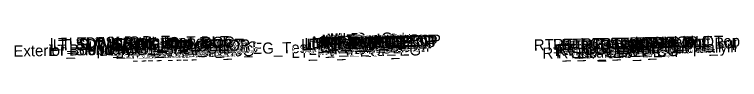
# Model space of a CAD drawing. Extents: x 118 to 4243, y 0 to 9511.
# Drawn here: x 1130.7 to 1260.3, y 1500.7 to 1505.9 of the extents above; entities that cross this region are included whole.
import ezdxf

# ---------------------------------------------------------------- set-up
doc = ezdxf.new("R2010")
doc.units = 0
doc.layers.add('Scratch_Level_0', color=7, linetype='Continuous')

msp = doc.modelspace()

# ---------------------------------------------------------------- texts
at = {"layer": 'Scratch_Level_0'}
for s, p in [('LT_SDWK_Out_Top', (1137.01, 1502.91)), ('LT_SDWK_Out_Bot', (1137.04, 1502.58)), ('LT_Sub_Trench_Out_DLT', (1137.57, 1502.67)), ('LT_CSLP_Pnt', (1140.44, 1502.99)), ('LT_SDWK_In_Top', (1143.63, 1502.85)), ('LT_CG_Top_Face', (1147.53, 1502.75)), ('LT_CG_Top_BOC', (1148.05, 1502.77)), ('LT_PV2_IEEOP', (1181.97, 1502.76)), ('LT_PV1_IEEOP', (1182.54, 1502.9)), ('LT_PV2_PGL1', (1182.9, 1502.78)), ('LT_PV2_PGL', (1183.23, 1502.79)), ('LT_PV1_PGL', (1183.8, 1503.05)), ('MI_Face In', (1183.92, 1503.22)), ('RT_PV2_OEEOP', (1185.28, 1502.99)), ('RT_PV3_OEEOP', (1185.28, 1502.66)), ('MI_Top In', (1185.63, 1503.49)), ('RT_PV1_OEEOP', (1185.85, 1503.13)), ('RT_PV2_IEEOP', (1185.93, 1503)), ('MI_Face Out', (1186.28, 1503.43)), ('MI_Top Out', (1186.49, 1503.7)), ('RT_PV1_IEEOP', (1186.49, 1503.14)), ('RT_PV2_PGL1', (1186.86, 1503.02)), ('RT_PV3_PGL1', (1186.86, 1502.69)), ('MI_Crown', (1187.09, 1503.76)), ('RT_PV2_PGL', (1187.19, 1503.03)), ('MI_Bot Out', (1187.28, 1503.28)), ('RT_PV1_PGL', (1187.75, 1503.29)), ('RT_Sub_Trench_Out_DLT', (1223.56, 1502.67)), ('RT_CG_Top_Face', (1226.99, 1502.74)), ('RT_CG_Top_BOC', (1228.51, 1502.76)), ('RT_SDWK_In_Top', (1232.08, 1502.85)), ('RT_SDWK_Out_Top', (1235.46, 1502.91)), ('RT_SDWK_Out_Bot', (1235.49, 1502.58)), ('RT_Shld_O', (1241.81, 1503.03)), ('CSLP_Pnt', (1242.64, 1503.05)), ('Exterior Boundary', (1130.51, 1501.57)), ('LT_Slope_Fill', (1136.89, 1501.7)), ('LT_SDWK_In_Bot', (1143.66, 1502.51)), ('LT_CG1_Shelf_Out', (1145.82, 1501.71)), ('LT_PV_Sub_Tie_Out', (1147.23, 1501.79)), ('LT_CG_Bot_BOC', (1148.09, 1501.75)), ('LT_CG_Top_Gut', (1148.51, 1502.26)), ('LT_Sub_OEOT_CG', (1149.64, 1501.2)), ('LT_PV_OEEOP_EG', (1149.82, 1501.84)), ('LT_PV2_OEEOP', (1151.58, 1502.16)), ('LT_PV3_OEEOP', (1151.58, 1501.82)), ('LT_PV1_OEEOP', (1152.15, 1502.29)), ('LT_CG_Bot_IE', (1152.19, 1501.84)), ('LT_PV2_OEOT', (1152.45, 1502.17)), ('LT_PV3_OEOT', (1152.45, 1501.84)), ('LT_PV1_OEOT', (1153.01, 1502.44)), ('LT_PV_EG_TestPt', (1163.56, 1501.86)), ('LT_PV_IEEOP_EG', (1180.21, 1501.34)), ('LT_PV3_IEEOP', (1181.97, 1502.43)), ('LT_PV3_PGL1', (1182.9, 1502.45)), ('LT_PV3_PGL', (1183.23, 1502.46)), ('LT_PV4_PGL', (1183.23, 1501.87)), ('RT_Sub_OEEOP', (1185.19, 1502.07)), ('RT_PV4_PGL', (1187.19, 1502.11)), ('RT_Sub_OEOT_CG', (1225.1, 1501.2)), ('RT_CG1_Shelf_Out', (1227.28, 1501.71)), ('RT_CG_Bot_IE', (1227.64, 1501.83)), ('RT_PV2_OEOT', (1227.9, 1502.17)), ('RT_PV3_OEOT', (1227.9, 1501.84)), ('RT_CG_Top_Gut', (1227.96, 1502.26)), ('RT_PV1_OEOT', (1228.46, 1502.43)), ('RT_CG_Bot_BOC', (1228.54, 1501.75)), ('RT_SDWK_In_Bot', (1232.11, 1502.51)), ('Exterior Boundary', (1236.75, 1501.93)), ('RT_Slope_Fill', (1243.07, 1502.06)), ('LT_Sub_OEOP', (1148.79, 1501.18)), ('LT_Sub_OEEOP', (1151.48, 1501.24)), ('LT_Sub_OEOT', (1152.35, 1501.26)), ('RT_Sub_OEOT', (1227.8, 1501.25)), ('RT_Sub_OEOP', (1231.43, 1501.18))]:
    msp.add_text(s, height=2, rotation=1.1458, dxfattribs=at).set_placement(p)

doc.saveas('drawing.dxf')
